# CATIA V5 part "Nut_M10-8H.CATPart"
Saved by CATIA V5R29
Part number: Nut_M10-8H
Source: Unknown
Bounding box of the stored display mesh (mm): x -4 to 4, y -8.5 to 8.5, z -9.815 to 9.815
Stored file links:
  C:\가치같이\SmartFactory_BoxErectorConveyor\Boxing(over)\Nut_M10-8H.CATPart
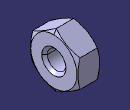
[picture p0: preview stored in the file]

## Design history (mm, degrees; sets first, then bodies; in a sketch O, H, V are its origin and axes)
Body1 (main body)
  Solid1 "PartBody": solid without history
